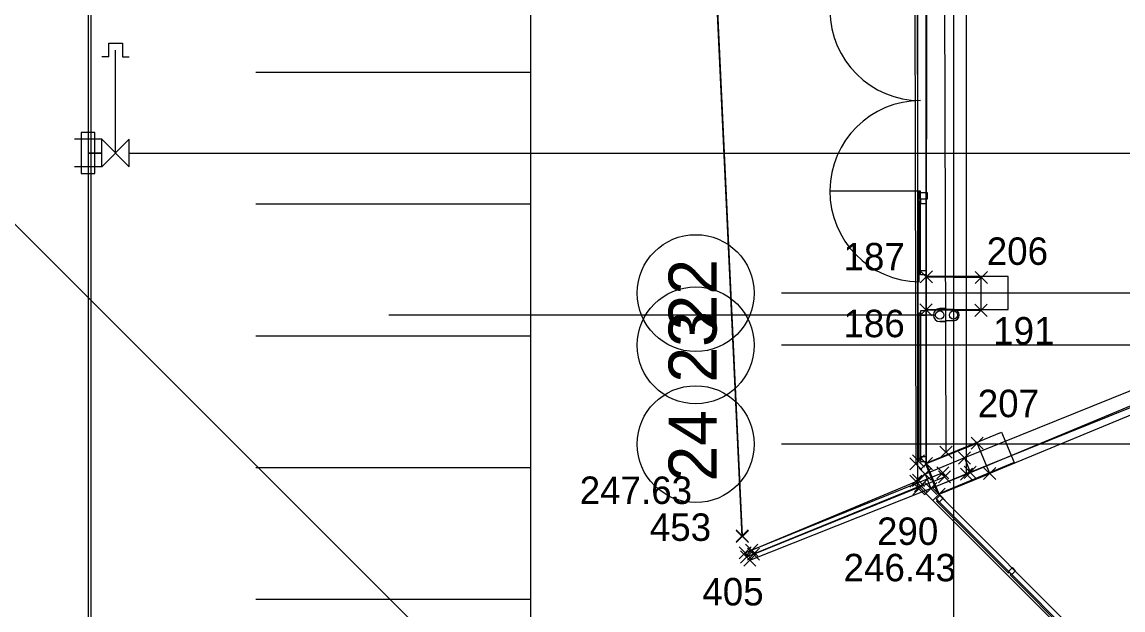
# Model space of a CAD drawing. Extents: x -264205 to -263659, y -1242401 to -1242060.
# Drawn here: x -263925.35 to -263905.31, y -1242229.65 to -1242218.95 of the extents above; entities that cross this region are included whole.
import ezdxf

# ---------------------------------------------------------------- set-up
doc = ezdxf.new("R2010")
doc.units = 0
for name, color, linetype in [('BOD_CISLO', 7, 'Continuous'), ('BOD_SYMBOL', 7, 'Continuous'), ('BOD_VYSKA', 7, 'Continuous'), ('KFA_SO_10-1_BETONOVE_STLPY', 7, 'Continuous'), ('KFA_SO_10-1_PLACHTY', 7, 'Continuous'), ('KFA_SO_10-1_STRECHY', 7, 'Continuous'), ('KFA_SO_10-1_TRIBUNA_A_OBVOD', 7, 'Continuous'), ('KFA_SO_10-1_ZABRADLIE_STADION', 7, 'Continuous'), ('OBRUBNIKY_KOMUNIKACIE_PROJEKT', 7, 'Continuous'), ('OSI_STAVBY_KFA', 7, 'Continuous'), ('SITUACIA_DSP_2D', 7, 'Continuous'), ('TDZ_VODOROVNE_PROJEKT', 7, 'Continuous')]:
    doc.layers.add(name, color=color, linetype=linetype)

msp = doc.modelspace()

# ---------------------------------------------------------------- linework, layer by layer
at = {"layer": 'BOD_SYMBOL'}
for p, q in [((-263908.997, -1242223.697), (-263908.776, -1242223.475)), ((-263908.776, -1242223.697), (-263908.997, -1242223.475)), ((-263907.997, -1242223.708), (-263907.776, -1242223.487)), ((-263907.776, -1242223.708), (-263907.997, -1242223.487)), ((-263909.003, -1242224.296), (-263908.781, -1242224.076)), ((-263908.781, -1242224.296), (-263909.003, -1242224.076)), ((-263908.003, -1242224.308), (-263907.781, -1242224.086)), ((-263907.781, -1242224.308), (-263908.003, -1242224.086)), ((-263908.072, -1242226.725), (-263907.851, -1242226.505)), ((-263907.851, -1242226.725), (-263908.072, -1242226.505)), ((-263909.142, -1242227.051), (-263908.921, -1242226.829)), ((-263908.921, -1242227.051), (-263909.142, -1242226.829)), ((-263908.641, -1242226.89), (-263908.42, -1242226.67)), ((-263908.42, -1242226.89), (-263908.641, -1242226.67)), ((-263908.305, -1242226.995), (-263908.084, -1242226.774)), ((-263908.084, -1242226.995), (-263908.305, -1242226.774)), ((-263909.191, -1242227.1), (-263908.97, -1242226.879)), ((-263908.97, -1242227.1), (-263909.191, -1242226.879)), ((-263908.997, -1242227.097), (-263908.776, -1242226.877)), ((-263908.776, -1242227.097), (-263908.997, -1242226.877)), ((-263908.997, -1242227.097), (-263908.776, -1242226.877)), ((-263908.776, -1242227.097), (-263908.997, -1242226.877)), ((-263908.199, -1242227.255), (-263907.978, -1242227.034)), ((-263907.978, -1242227.255), (-263908.199, -1242227.034)), ((-263909.19, -1242227.417), (-263908.969, -1242227.195)), ((-263908.969, -1242227.417), (-263909.19, -1242227.195)), ((-263909.142, -1242227.401), (-263908.921, -1242227.181)), ((-263908.921, -1242227.401), (-263909.142, -1242227.181)), ((-263909.019, -1242227.289), (-263908.799, -1242227.068)), ((-263908.799, -1242227.289), (-263909.019, -1242227.068)), ((-263908.699, -1242227.264), (-263908.478, -1242227.042)), ((-263908.478, -1242227.264), (-263908.699, -1242227.042)), ((-263908.667, -1242227.339), (-263908.446, -1242227.117)), ((-263908.446, -1242227.339), (-263908.667, -1242227.117)), ((-263908.268, -1242227.289), (-263908.046, -1242227.069)), ((-263908.046, -1242227.289), (-263908.268, -1242227.069)), ((-263907.845, -1242227.275), (-263907.623, -1242227.055)), ((-263907.623, -1242227.275), (-263907.845, -1242227.055)), ((-263909.136, -1242227.555), (-263908.915, -1242227.333)), ((-263908.915, -1242227.555), (-263909.136, -1242227.333)), ((-263909.101, -1242227.499), (-263908.879, -1242227.279)), ((-263908.879, -1242227.499), (-263909.101, -1242227.279)), ((-263908.916, -1242227.549), (-263908.695, -1242227.328)), ((-263908.695, -1242227.549), (-263908.916, -1242227.328)), ((-263908.768, -1242227.656), (-263908.546, -1242227.434)), ((-263908.546, -1242227.656), (-263908.768, -1242227.434)), ((-263908.768, -1242227.656), (-263908.546, -1242227.434)), ((-263908.546, -1242227.656), (-263908.768, -1242227.434)), ((-263912.349, -1242228.413), (-263912.128, -1242228.191)), ((-263912.128, -1242228.413), (-263912.349, -1242228.191)), ((-263912.348, -1242228.424), (-263912.127, -1242228.203)), ((-263912.127, -1242228.424), (-263912.348, -1242228.203)), ((-263912.296, -1242228.721), (-263912.074, -1242228.499)), ((-263912.074, -1242228.721), (-263912.296, -1242228.499)), ((-263912.267, -1242228.796), (-263912.046, -1242228.576)), ((-263912.046, -1242228.796), (-263912.267, -1242228.576)), ((-263912.212, -1242228.853), (-263911.991, -1242228.632)), ((-263911.991, -1242228.853), (-263912.212, -1242228.632)), ((-263912.176, -1242228.674), (-263911.954, -1242228.454)), ((-263911.954, -1242228.674), (-263912.176, -1242228.454)), ((-263912.145, -1242228.745), (-263911.924, -1242228.525)), ((-263911.924, -1242228.745), (-263912.145, -1242228.525))]:
    msp.add_line(p, q, dxfattribs=at)
at = {"layer": 'KFA_SO_10-1_BETONOVE_STLPY'}
for p, q in [((-263908.892, -1242224.186), (-263908.887, -1242223.586)), ((-263908.887, -1242223.586), (-263907.887, -1242223.597)), ((-263907.892, -1242224.197), (-263907.887, -1242223.597)), ((-263908.892, -1242224.186), (-263907.892, -1242224.197)), ((-263908.887, -1242226.987), (-263907.961, -1242226.615)), ((-263907.734, -1242227.165), (-263907.961, -1242226.615)), ((-263908.657, -1242227.545), (-263908.887, -1242226.987)), ((-263908.657, -1242227.545), (-263907.734, -1242227.165))]:
    msp.add_line(p, q, dxfattribs=at)
at = {"layer": 'KFA_SO_10-1_PLACHTY'}
for p, q in [((-263908.632, -1242196.778), (-263908.53, -1242226.78)), ((-263909.149, -1242196.844), (-263909.08, -1242226.989)), ((-263909.031, -1242226.94), (-263909.097, -1242199.693))]:
    msp.add_line(p, q, dxfattribs=at)
for points in [[(-263912.238, -1242228.302), (-263912.237, -1242228.313), (-263913.727, -1242196.804), (-263913.722, -1242196.8)], [(-263912.156, -1242228.686), (-263912.185, -1242228.61), (-263909.031, -1242227.291), (-263909.079, -1242227.306), (-263909.025, -1242227.444), (-263908.99, -1242227.389)]]:
    msp.add_lwpolyline(points, close=True, dxfattribs=at)
msp.add_lwpolyline([(-263908.557, -1242227.228), (-263908.589, -1242227.153), (-263912.065, -1242228.564), (-263912.035, -1242228.635), (-263908.557, -1242227.228)], dxfattribs=at)
at = {"layer": 'KFA_SO_10-1_STRECHY'}
msp.add_line((-263908.157, -1242227.179), (-263908.136, -1242101.59), dxfattribs=at)
msp.add_lwpolyline([(-263912.101, -1242228.742), (-263908.157, -1242227.179), (-263889.533, -1242219.411)], dxfattribs=at)
at = {"layer": 'KFA_SO_10-1_TRIBUNA_A_OBVOD'}
msp.add_line((-263908.657, -1242227.545), (-263892.039, -1242220.661), dxfattribs=at)
msp.add_lwpolyline([(-263908.657, -1242227.545), (-263908.887, -1242226.987), (-263908.871, -1242203.378)], dxfattribs=at)
at = {"layer": 'KFA_SO_10-1_ZABRADLIE_STADION'}
for p, q in [((-263892.159, -1242220.397), (-263908.194, -1242226.884)), ((-263908.089, -1242227.144), (-263892.055, -1242220.657)), ((-263908.194, -1242226.884), (-263908.909, -1242227.178)), ((-263908.194, -1242226.884), (-263908.089, -1242227.144)), ((-263908.909, -1242227.178), (-263908.806, -1242227.438)), ((-263908.806, -1242227.438), (-263908.089, -1242227.144))]:
    msp.add_line(p, q, dxfattribs=at)
at = {"layer": 'OBRUBNIKY_KOMUNIKACIE_PROJEKT'}
for p, q in [((-263909.043, -1242227.382), (-263909.043, -1242196.333)), ((-263894.968, -1242241.457), (-263909.043, -1242227.382))]:
    msp.add_line(p, q, dxfattribs=at)
at = {"layer": 'OSI_STAVBY_KFA'}
for p, q in [((-263908.393, -1242083.237), (-263908.393, -1242246.707)), ((-263792.653, -1242223.882), (-263911.523, -1242223.882)), ((-263792.653, -1242224.832), (-263911.523, -1242224.832)), ((-263792.653, -1242226.632), (-263911.523, -1242226.632))]:
    msp.add_line(p, q, dxfattribs=at)
for centre in [(-263913.085, -1242223.882), (-263913.085, -1242224.832), (-263913.085, -1242226.632)]:
    msp.add_circle(centre, 1.064, dxfattribs=at)
at = {"layer": 'SITUACIA_DSP_2D'}
for p, q in [((-263924.143, -1242185.14), (-263924.143, -1242250.14)), ((-263909.043, -1242227.382), (-263909.043, -1242196.333)), ((-263908.893, -1242226.995), (-263908.893, -1242203.332)), ((-263923.768, -1242219.582), (-263923.768, -1242219.332)), ((-263923.768, -1242219.332), (-263923.518, -1242219.332)), ((-263923.518, -1242219.332), (-263923.518, -1242219.582)), ((-263923.768, -1242219.582), (-263923.893, -1242219.582)), ((-263923.643, -1242221.332), (-263923.643, -1242219.457)), ((-263923.518, -1242219.582), (-263923.393, -1242219.582)), ((-263924.018, -1242220.957), (-263924.268, -1242220.957)), ((-263924.268, -1242220.957), (-263924.268, -1242221.707)), ((-263924.018, -1242221.707), (-263924.018, -1242220.957)), ((-263923.893, -1242221.082), (-263924.393, -1242221.082)), ((-263923.893, -1242221.582), (-263923.893, -1242221.082)), ((-263923.893, -1242221.082), (-263923.393, -1242221.582)), ((-263923.393, -1242221.082), (-263923.893, -1242221.582)), ((-263923.393, -1242221.582), (-263923.393, -1242221.082)), ((-263924.143, -1242221.332), (-263923.893, -1242221.332)), ((-263923.893, -1242221.332), (-263924.143, -1242221.332)), ((-263923.393, -1242221.332), (-263903.343, -1242221.332)), ((-263923.893, -1242221.582), (-263924.393, -1242221.582)), ((-263924.268, -1242221.707), (-263924.018, -1242221.707)), ((-263916.414, -1242231.691), (-263926.24, -1242221.865)), ((-263908.993, -1242222.027), (-263910.643, -1242222.027)), ((-263909.018, -1242223.677), (-263909.018, -1242222.027)), ((-263908.993, -1242222.052), (-263908.993, -1242222.027)), ((-263909.018, -1242222.212), (-263909.018, -1242223.512)), ((-263908.993, -1242222.212), (-263909.018, -1242222.212)), ((-263908.993, -1242222.052), (-263908.873, -1242222.052)), ((-263908.993, -1242222.172), (-263908.993, -1242222.052)), ((-263908.893, -1242222.172), (-263908.993, -1242222.172)), ((-263908.993, -1242222.172), (-263908.993, -1242222.212)), ((-263908.873, -1242222.172), (-263908.993, -1242222.172)), ((-263908.993, -1242223.512), (-263908.993, -1242222.212)), ((-263908.993, -1242222.212), (-263908.993, -1242222.252)), ((-263908.893, -1242222.252), (-263908.893, -1242222.172)), ((-263908.873, -1242222.052), (-263908.873, -1242222.172)), ((-263908.993, -1242222.252), (-263908.893, -1242222.252)), ((-263909.018, -1242223.512), (-263908.993, -1242223.512)), ((-263908.993, -1242223.512), (-263908.993, -1242223.472)), ((-263908.993, -1242223.472), (-263908.893, -1242223.472)), ((-263908.993, -1242223.552), (-263908.993, -1242223.512)), ((-263908.893, -1242223.552), (-263908.993, -1242223.552)), ((-263907.398, -1242223.582), (-263908.898, -1242223.582)), ((-263908.898, -1242223.582), (-263908.898, -1242224.182)), ((-263908.893, -1242223.472), (-263908.893, -1242223.552)), ((-263907.398, -1242224.182), (-263907.398, -1242223.582)), ((-263908.893, -1242224.202), (-263908.993, -1242224.202)), ((-263908.993, -1242224.202), (-263908.993, -1242224.242)), ((-263908.898, -1242224.182), (-263907.398, -1242224.182)), ((-263908.893, -1242224.282), (-263908.893, -1242224.202)), ((-263908.532, -1242224.165), (-263908.643, -1242224.165)), ((-263908.518, -1242224.179), (-263908.532, -1242224.165)), ((-263908.393, -1242224.179), (-263908.518, -1242224.179)), ((-263908.718, -1242224.282), (-263918.67, -1242224.282)), ((-263909.018, -1242226.892), (-263909.018, -1242224.242)), ((-263909.018, -1242224.242), (-263908.993, -1242224.242)), ((-263908.993, -1242224.242), (-263908.993, -1242226.892)), ((-263908.993, -1242224.242), (-263908.993, -1242224.282)), ((-263908.993, -1242224.282), (-263908.893, -1242224.282)), ((-263908.643, -1242224.399), (-263908.532, -1242224.399)), ((-263908.532, -1242224.399), (-263908.643, -1242224.399)), ((-263908.518, -1242224.385), (-263908.532, -1242224.399)), ((-263908.393, -1242224.385), (-263908.518, -1242224.385)), ((-263908.903, -1242226.985), (-263907.518, -1242226.411)), ((-263907.518, -1242226.411), (-263907.288, -1242226.966)), ((-263908.993, -1242226.892), (-263909.018, -1242226.892)), ((-263908.893, -1242226.865), (-263908.993, -1242226.865)), ((-263908.993, -1242226.865), (-263908.993, -1242226.905)), ((-263908.993, -1242226.905), (-263908.993, -1242226.945)), ((-263908.993, -1242226.945), (-263908.893, -1242226.945)), ((-263908.674, -1242227.54), (-263908.903, -1242226.985)), ((-263908.893, -1242226.945), (-263908.893, -1242226.865)), ((-263908.893, -1242226.995), (-263908.663, -1242227.55)), ((-263907.288, -1242226.966), (-263908.674, -1242227.54)), ((-263894.968, -1242241.457), (-263909.043, -1242227.382)), ((-263908.709, -1242227.631), (-263908.638, -1242227.56)), ((-263908.68, -1242227.659), (-263908.709, -1242227.631)), ((-263908.663, -1242227.55), (-263895.135, -1242241.078)), ((-263908.581, -1242227.617), (-263908.652, -1242227.688)), ((-263908.638, -1242227.56), (-263908.581, -1242227.617)), ((-263908.685, -1242227.654), (-263908.703, -1242227.672)), ((-263908.703, -1242227.672), (-263907.395, -1242228.98)), ((-263907.377, -1242228.963), (-263908.685, -1242227.654)), ((-263908.652, -1242227.688), (-263908.68, -1242227.659)), ((-263907.395, -1242228.98), (-263907.377, -1242228.963)), ((-263907.39, -1242228.95), (-263907.319, -1242228.879)), ((-263907.361, -1242228.978), (-263907.39, -1242228.95)), ((-263907.363, -1242229.012), (-263907.345, -1242228.994)), ((-263906.055, -1242230.32), (-263907.363, -1242229.012)), ((-263907.333, -1242229.007), (-263907.361, -1242228.978)), ((-263907.345, -1242228.994), (-263906.037, -1242230.303)), ((-263907.262, -1242228.936), (-263907.333, -1242229.007)), ((-263907.319, -1242228.879), (-263907.262, -1242228.936))]:
    msp.add_line(p, q, dxfattribs=at)
for centre in [(-263908.643, -1242224.282), (-263908.393, -1242224.282)]:
    msp.add_circle(centre, 0.075, dxfattribs=at)
for centre, radius, start, end in [((-263908.993, -1242218.727), 1.65, 90.8682, 270), ((-263908.993, -1242222.027), 1.65, 90, 269.1318), ((-263908.643, -1242224.282), 0.117, 90, 270), ((-263908.393, -1242224.282), 0.103, 270, 90)]:
    msp.add_arc(centre, radius, start, end, dxfattribs=at)
at = {"layer": 'TDZ_VODOROVNE_PROJEKT'}
for p, q in [((-263924.088, -1242241.458), (-263924.093, -1242087.307)), ((-263916.093, -1242187.557), (-263916.093, -1242241.458)), ((-263921.093, -1242219.857), (-263916.093, -1242219.857)), ((-263921.093, -1242222.257), (-263916.093, -1242222.257)), ((-263921.093, -1242224.657), (-263916.093, -1242224.657)), ((-263921.093, -1242227.057), (-263916.093, -1242227.057)), ((-263921.093, -1242229.457), (-263916.093, -1242229.457))]:
    msp.add_line(p, q, dxfattribs=at)

# ---------------------------------------------------------------- texts
at = {"layer": 'BOD_CISLO'}
for s, p in [('187', (-263910.395, -1242223.469)), ('206', (-263907.788, -1242223.368)), ('186', (-263910.396, -1242224.685)), ('191', (-263907.671, -1242224.818)), ('207', (-263907.952, -1242226.141)), ('453', (-263913.92, -1242228.393)), ('290', (-263909.785, -1242228.467)), ('405', (-263912.964, -1242229.568))]:
    msp.add_text(s, height=0.5, dxfattribs=at).set_placement(p)
at = {"layer": 'BOD_VYSKA'}
for s, p in [('247.63', (-263915.196, -1242227.721)), ('246.43', (-263910.394, -1242229.129))]:
    msp.add_text(s, height=0.5, dxfattribs=at).set_placement(p)
at = {"layer": 'OSI_STAVBY_KFA'}
for s, p in [('22', (-263912.704, -1242224.562)), ('23', (-263912.704, -1242225.512)), ('24', (-263912.704, -1242227.312))]:
    msp.add_text(s, height=0.875, rotation=90, dxfattribs=at).set_placement(p)

doc.saveas('drawing.dxf')
